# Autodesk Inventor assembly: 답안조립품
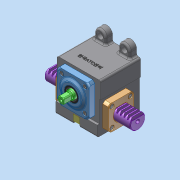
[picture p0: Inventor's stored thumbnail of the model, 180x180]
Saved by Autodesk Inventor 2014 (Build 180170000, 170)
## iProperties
Created: 2025-06
Part Number: 답안조립품
Document SubType Name: Assembly
Designer: dg
Mass: 1831.54 g
Surface Area: 1255.94 cm^2
Volume: 477.957 cm^3
Density: 3.83202 g/cm^3
Author: dg
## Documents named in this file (10)
- C:\Users\dg\Desktop\650603V1010\답안조립품.iam
- C:\Users\dg\Desktop\650603V1010\가져온 구성요소\본체\본체.ipt
- C:\Users\dg\Desktop\650603V1010\가져온 구성요소\깊음 홈 볼 베어링 6202\깊음 홈 볼 베어링 6202.ipt
- C:\Users\dg\Desktop\650603V1010\가져온 구성요소\피니언 축\피니언 축.ipt
- C:\Users\dg\Desktop\650603V1010\가져온 구성요소\커버\커버.ipt
- C:\Users\dg\Desktop\650603V1010\가져온 구성요소\오일 실 15 25 4\오일 실 15 25 4.ipt
- C:\Users\dg\Desktop\650603V1010\가져온 구성요소\수지 부시\수지 부시.ipt
- C:\Users\dg\Desktop\650603V1010\가져온 구성요소\육각 소켓 머리 볼트 M4x10\육각 소켓 머리 볼트 M4x10.ipt
- C:\Users\dg\Desktop\650603V1010\가져온 구성요소\래크\래크.ipt
- C:\Users\dg\Desktop\650603V1010\가져온 구성요소\스톱퍼\스톱퍼.ipt
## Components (1 placed, 1 different names)
1. 피니언 축:1
